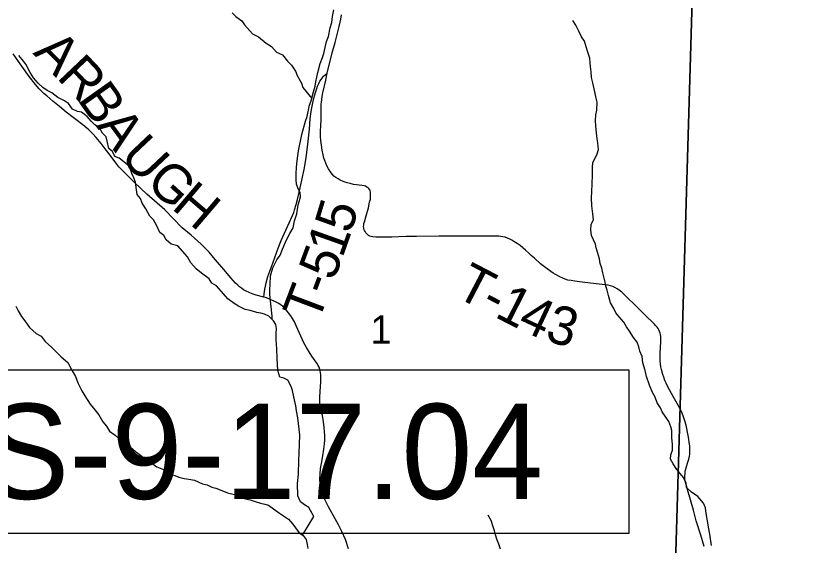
# Model space of a CAD drawing. Extents: x 0 to 34, y 0 to 22.
# Drawn here: x 14.55 to 15.724, y 18.969 to 19.748 of the extents above; entities that cross this region are included whole.
import ezdxf

# ---------------------------------------------------------------- set-up
doc = ezdxf.new("R2010")
doc.units = 0
for name, color, linetype in [('GM_X_Corporation', 7, 'Continuous'), ('GM_X_Minor_River', 7, 'Continuous'), ('GM_X_Section_Text', 7, 'Continuous'), ('GM_X_Township_Road', 7, 'Continuous'), ('GM_X_Township_Road_Text', 7, 'Continuous'), ('SH_Text', 7, 'Continuous')]:
    doc.layers.add(name, color=color, linetype=linetype)

msp = doc.modelspace()

# ---------------------------------------------------------------- linework, layer by layer
at = {"layer": 'GM_X_Corporation'}
for points in [[(14.532, 19.9321), (15.5496, 19.9206), (15.5197, 18.9088), (14.5125, 18.9236)], [(16.7598, 19.9006), (16.7485, 18.8896), (16.5138, 18.8938), (15.5197, 18.9088), (15.5496, 19.9206)]]:
    msp.add_lwpolyline(points, close=True, dxfattribs=at)
at = {"layer": 'GM_X_Minor_River'}
for points in [[(14.927, 19.301), (14.927, 19.306), (14.9234, 19.338), (14.9234, 19.3459), (14.9238, 19.3524), (14.9242, 19.3653), (14.9277, 19.3771), (14.9338, 19.3888), (14.9388, 19.3957), (14.9422, 19.4044), (14.948, 19.4184), (14.953, 19.4279), (14.9579, 19.4362), (14.9595, 19.4465), (14.9633, 19.4567), (14.9653, 19.47), (14.9672, 19.4761), (14.9684, 19.4818), (14.968, 19.4879), (14.965, 19.4936), (14.9628, 19.5004), (14.962, 19.5069), (14.9621, 19.5153), (14.9625, 19.5251), (14.9637, 19.5346), (14.9656, 19.5495), (14.9703, 19.5734), (14.9757, 19.5931), (14.9784, 19.5999), (14.9819, 19.6167), (14.9842, 19.6231), (14.9876, 19.6364), (14.99, 19.6444), (14.9911, 19.6508), (14.9942, 19.6645), (14.9977, 19.6778), (15.0011, 19.6869), (15.0027, 19.6926), (15.0066, 19.7104), (15.01, 19.7176), (15.0123, 19.7305), (15.0146, 19.7385), (15.0154, 19.7469), (15.0178, 19.7567)], [(14.8679, 19.7523), (14.8735, 19.747), (14.8822, 19.7409), (14.886, 19.7348), (14.8981, 19.7215), (14.9068, 19.7172), (14.9181, 19.7077), (14.9257, 19.7031), (14.9333, 19.6947), (14.9423, 19.6905), (14.9495, 19.6814), (14.9552, 19.6753), (14.9612, 19.6665), (14.9638, 19.6604), (14.9699, 19.649), (14.9721, 19.6425), (14.985, 19.6265)], [(15.4049, 19.609), (15.405, 19.6208), (15.4039, 19.6269), (15.4016, 19.6364), (15.3986, 19.6494), (15.3968, 19.6573), (15.3961, 19.6657), (15.3953, 19.6733), (15.395, 19.679), (15.3942, 19.6858), (15.3909, 19.6961), (15.3864, 19.7106), (15.3822, 19.7174), (15.3781, 19.7254), (15.3736, 19.7342), (15.3694, 19.741)], [(14.9717, 18.9836), (14.9884, 19.0113), (14.9808, 19.0243), (14.9744, 19.0281), (14.9687, 19.0327), (14.9646, 19.0414), (14.9643, 19.0597), (14.9655, 19.0733), (14.9663, 19.0942), (14.9668, 19.1041), (14.9672, 19.1178), (14.9676, 19.1307), (14.9665, 19.1398), (14.9647, 19.1562), (14.9625, 19.1668), (14.9617, 19.174), (14.9588, 19.1874), (14.9569, 19.1965), (14.9547, 19.2026), (14.9498, 19.2117), (14.9441, 19.2148), (14.938, 19.2163), (14.9354, 19.2262), (14.9343, 19.2444), (14.9336, 19.2577), (14.9326, 19.2718), (14.9326, 19.2805), (14.9334, 19.2878), (14.9323, 19.2935), (14.9289, 19.2992), (14.9217, 19.306), (14.9157, 19.3091), (14.91, 19.3106), (14.9043, 19.3114), (14.8944, 19.3141), (14.8872, 19.3157), (14.8774, 19.3206), (14.8709, 19.3245), (14.8615, 19.3313), (14.8551, 19.339), (14.8449, 19.3508), (14.8381, 19.3546), (14.8339, 19.3611), (14.823, 19.3691), (14.815, 19.3756), (14.8071, 19.3847), (14.8022, 19.3931), (14.7882, 19.4095), (14.778, 19.4122), (14.7708, 19.4183), (14.7674, 19.4248), (14.7617, 19.429), (14.7569, 19.4389), (14.752, 19.4476), (14.747, 19.4533), (14.741, 19.464), (14.7354, 19.4724), (14.7331, 19.4792), (14.7282, 19.4853), (14.7271, 19.4918), (14.7256, 19.5032), (14.7234, 19.5097), (14.7204, 19.5158), (14.7174, 19.5257), (14.7083, 19.5333), (14.7015, 19.5386), (14.6954, 19.5409), (14.6921, 19.5482), (14.6864, 19.5527), (14.6842, 19.5634), (14.6827, 19.5699), (14.677, 19.5752), (14.6725, 19.5832), (14.666, 19.5878), (14.6604, 19.5931), (14.6547, 19.6), (14.6464, 19.6061), (14.6403, 19.6072), (14.6331, 19.6107), (14.6271, 19.6191), (14.6214, 19.6229), (14.6116, 19.6279), (14.6025, 19.6347), (14.5957, 19.6382), (14.5893, 19.6424), (14.5825, 19.6489), (14.5757, 19.6569), (14.5708, 19.6645), (14.5644, 19.6771), (14.5587, 19.6839), (14.5538, 19.6896)], [(15.5736, 18.9682), (15.5711, 18.9849), (15.5688, 18.9955), (15.5681, 19.002), (15.5655, 19.0153), (15.5648, 19.0237), (15.5618, 19.0309), (15.5531, 19.0404), (15.544, 19.0469), (15.5368, 19.0538), (15.5361, 19.0603), (15.532, 19.0683), (15.5225, 19.0804), (15.5169, 19.0884), (15.5131, 19.0953), (15.5135, 19.1018), (15.5158, 19.1086), (15.5162, 19.1169), (15.5151, 19.1272), (15.5152, 19.1375), (15.5137, 19.1432), (15.5107, 19.1508), (15.505, 19.1588), (15.5009, 19.1653), (15.4983, 19.171), (15.4937, 19.1782), (15.4904, 19.1866), (15.4866, 19.1938), (15.4821, 19.2045), (15.4776, 19.217), (15.4757, 19.2258), (15.4724, 19.2372), (15.4716, 19.2467), (15.4679, 19.2547), (15.4664, 19.2608), (15.4638, 19.2676), (15.4585, 19.2748), (15.4528, 19.284), (15.4483, 19.2905), (15.4442, 19.2973), (15.4377, 19.3049), (15.4325, 19.3107), (15.4295, 19.3171), (15.4249, 19.3255), (15.4219, 19.3362), (15.4201, 19.3441), (15.4178, 19.3502), (15.4163, 19.3578), (15.4149, 19.3639), (15.4134, 19.3696), (15.4119, 19.3765), (15.4096, 19.3837), (15.4085, 19.3905), (15.4055, 19.4001), (15.4037, 19.4065), (15.4025, 19.4122), (15.3999, 19.4183), (15.3969, 19.4248), (15.3958, 19.4331), (15.3962, 19.4415), (15.4, 19.4476), (15.3989, 19.4567), (15.3975, 19.4685), (15.3968, 19.4806), (15.3972, 19.4886), (15.398, 19.5012), (15.3984, 19.5133), (15.3985, 19.5255), (15.3989, 19.5316), (15.405, 19.5448), (15.4069, 19.5513), (15.4062, 19.5612), (15.4051, 19.5669), (15.4037, 19.5802), (15.4033, 19.5866), (15.4029, 19.5935), (15.4034, 19.6026), (15.4049, 19.609)], [(14.5495, 19.3207), (14.5529, 19.3138), (14.5578, 19.3055), (14.5627, 19.299), (14.5695, 19.2891), (14.5797, 19.2803), (14.5869, 19.2765), (14.593, 19.2688), (14.6028, 19.2597), (14.6164, 19.246), (14.6262, 19.2379), (14.6319, 19.2265), (14.6375, 19.217), (14.6409, 19.2079), (14.6439, 19.2018), (14.6469, 19.1961), (14.651, 19.1888), (14.659, 19.1763), (14.6661, 19.1679), (14.6718, 19.1606), (14.6778, 19.1504), (14.6831, 19.1439), (14.6876, 19.1367), (14.6956, 19.1309), (14.705, 19.1225), (14.7122, 19.1179), (14.7183, 19.113), (14.7258, 19.1069), (14.733, 19.1015), (14.7398, 19.0958), (14.7455, 19.0927), (14.7572, 19.0843), (14.7671, 19.0801), (14.7765, 19.0736), (14.7837, 19.0713), (14.7894, 19.069), (14.7974, 19.0671), (14.8042, 19.0663), (14.8125, 19.0644), (14.8243, 19.059), (14.8311, 19.0575), (14.8379, 19.0544), (14.844, 19.0529), (14.8504, 19.0502), (14.861, 19.046), (14.8712, 19.0433), (14.8834, 19.0379), (14.8947, 19.0356), (14.9019, 19.0333), (14.9095, 19.0306), (14.916, 19.0294), (14.9216, 19.0279), (14.9288, 19.0225), (14.9375, 19.0161), (14.9451, 19.0111), (14.9508, 19.0073), (14.9572, 19), (14.9613, 18.9943), (14.9666, 18.9871), (14.9727, 18.9829), (14.9768, 18.9772), (14.9783, 18.9699), (14.9794, 18.9642)], [(15.2629, 18.9632), (15.2606, 18.9704), (15.2576, 18.9777), (15.2554, 18.9841), (15.2539, 18.9898), (15.252, 18.9959), (15.249, 19.0051), (15.2449, 19.013)]]:
    msp.add_lwpolyline(points, dxfattribs=at)
at = {"layer": 'GM_X_Township_Road'}
for points in [[(14.9992, 19.6187), (14.9993, 19.6206), (15.0006, 19.6295), (15.0015, 19.6347), (15.0056, 19.6536), (15.0077, 19.6637), (15.0153, 19.6938), (15.0196, 19.7087), (15.0254, 19.7324), (15.0279, 19.743), (15.0291, 19.7498)], [(14.9148, 19.3341), (14.9031, 19.337), (14.8974, 19.3389), (14.8929, 19.3407), (14.8886, 19.3428), (14.8848, 19.3449), (14.8816, 19.347), (14.879, 19.3491), (14.8762, 19.3514), (14.8728, 19.3544), (14.8693, 19.3583), (14.8662, 19.3623), (14.8558, 19.3746), (14.8464, 19.3855), (14.8407, 19.3925), (14.834, 19.4002), (14.8288, 19.4058), (14.8223, 19.412), (14.8076, 19.425), (14.7944, 19.4359), (14.7687, 19.4626), (14.7422, 19.4857), (14.7242, 19.5027), (14.7179, 19.509), (14.7124, 19.5144), (14.7085, 19.5184), (14.7051, 19.522), (14.7014, 19.526), (14.6982, 19.5298), (14.6882, 19.5428), (14.6809, 19.5522), (14.6751, 19.5602), (14.668, 19.5691), (14.6628, 19.5744), (14.6569, 19.5802), (14.6484, 19.5876), (14.6235, 19.6061), (14.6137, 19.6145), (14.6042, 19.6226), (14.5952, 19.6304), (14.5907, 19.634), (14.5838, 19.6406), (14.576, 19.6499), (14.5731, 19.6538), (14.5693, 19.6588), (14.5582, 19.6741), (14.5534, 19.6809), (14.5459, 19.6922)], [(14.9148, 19.3341), (14.9151, 19.3389), (14.916, 19.3459), (14.9168, 19.3502), (14.9181, 19.3552), (14.9207, 19.3643), (14.9235, 19.3722), (14.926, 19.3788), (14.9357, 19.4061), (14.9401, 19.4172), (14.9472, 19.4328), (14.9568, 19.4541), (14.9585, 19.4586), (14.9599, 19.4625), (14.9621, 19.4703), (14.9642, 19.4778), (14.9682, 19.4947), (14.9707, 19.5062), (14.9741, 19.5221), (14.9769, 19.539), (14.9795, 19.5594), (14.9819, 19.5815), (14.983, 19.5966), (14.9841, 19.6072), (14.9855, 19.6149), (14.9866, 19.6202), (14.989, 19.6301), (14.991, 19.6369), (14.9924, 19.6412), (14.9938, 19.6448), (14.9955, 19.6484), (14.9972, 19.6517), (14.9989, 19.6543), (15.0002, 19.6563), (15.0024, 19.6592), (15.0048, 19.6614), (15.0077, 19.6637)], [(15.4676, 19.3156), (15.4611, 19.322), (15.4488, 19.3342), (15.4414, 19.3412), (15.4377, 19.3443), (15.4348, 19.3463), (15.431, 19.3483), (15.428, 19.3495), (15.4246, 19.3507), (15.4213, 19.3514), (15.417, 19.3521), (15.4079, 19.3529), (15.3868, 19.3555), (15.3792, 19.3564), (15.3722, 19.3574), (15.3668, 19.3583), (15.3621, 19.359), (15.3583, 19.3603), (15.3544, 19.3619), (15.3503, 19.3638), (15.3468, 19.3657), (15.3437, 19.3675), (15.3406, 19.3695), (15.3316, 19.3756), (15.3255, 19.3801), (15.322, 19.3829), (15.3129, 19.3912), (15.3082, 19.3955), (15.3042, 19.3992), (15.2998, 19.4032), (15.2959, 19.4066), (15.292, 19.4098), (15.2872, 19.4132), (15.2826, 19.4161), (15.2795, 19.4179), (15.2765, 19.4195), (15.2733, 19.421), (15.2697, 19.4222), (15.2663, 19.423), (15.2606, 19.4237), (15.2553, 19.4238), (15.2131, 19.4236), (15.1867, 19.4238), (15.172, 19.4239), (15.1392, 19.4234), (15.1239, 19.4231), (15.1134, 19.4228), (15.1031, 19.4225), (15.0962, 19.4224), (15.0792, 19.4225), (15.0751, 19.4229), (15.0727, 19.4232), (15.0706, 19.424), (15.0688, 19.4249), (15.0673, 19.426), (15.066, 19.4272), (15.0648, 19.4286), (15.0635, 19.4304), (15.0628, 19.4322), (15.062, 19.4343), (15.0616, 19.4361), (15.0614, 19.4379), (15.0616, 19.4402), (15.062, 19.4426), (15.0626, 19.445), (15.0652, 19.4538), (15.0684, 19.4653), (15.0703, 19.4737), (15.0714, 19.478), (15.0718, 19.4816), (15.0716, 19.4883), (15.0712, 19.4903), (15.0704, 19.4921), (15.0693, 19.4937), (15.0681, 19.4949), (15.0663, 19.4961), (15.0642, 19.4972), (15.0624, 19.4978), (15.0587, 19.4985), (15.0511, 19.4992), (15.0466, 19.5), (15.0417, 19.5011), (15.0371, 19.5024), (15.0315, 19.5044), (15.0269, 19.5064), (15.0238, 19.508), (15.0204, 19.5102), (15.0178, 19.5123), (15.0156, 19.5145), (15.0135, 19.5169), (15.0115, 19.52), (15.0097, 19.5228), (15.0074, 19.5273), (15.0058, 19.5312), (15.0042, 19.5353), (15.003, 19.5388), (15.0018, 19.5436), (15.0005, 19.5502), (14.9995, 19.5578), (14.9986, 19.5646), (14.9981, 19.5707), (14.998, 19.5786), (14.9985, 19.5855), (14.9988, 19.5962), (14.9992, 19.6187)], [(15.0393, 18.9634), (15.0347, 18.9773), (15.0296, 18.9889), (15.0245, 18.9989), (15.0098, 19.0253), (15.0062, 19.0323), (15.0034, 19.0383), (15.002, 19.0418), (15.0008, 19.0462), (14.999, 19.0524), (14.9977, 19.0595), (14.9969, 19.0655), (14.9981, 19.0819), (14.9993, 19.0891), (15.0012, 19.1005), (15.0028, 19.1103), (15.0039, 19.1181), (15.0042, 19.1233), (15.0043, 19.1305), (15.004, 19.1356), (15.0035, 19.1428), (15.0021, 19.154), (15.0009, 19.1598), (14.9982, 19.1708), (14.9971, 19.1793), (14.9972, 19.187), (14.9973, 19.1952), (14.9986, 19.2094), (14.9987, 19.215), (14.9985, 19.2199), (14.9981, 19.2228), (14.9975, 19.2257), (14.997, 19.2277), (14.9958, 19.2309), (14.9946, 19.2334), (14.9928, 19.2366), (14.9851, 19.2473), (14.9827, 19.2509), (14.9773, 19.2597), (14.9737, 19.2668), (14.9627, 19.2907), (14.9597, 19.2978), (14.957, 19.3026), (14.9545, 19.3066), (14.951, 19.3111), (14.946, 19.3173), (14.9419, 19.3208), (14.9367, 19.3247), (14.9316, 19.3272), (14.9241, 19.3306), (14.9183, 19.3328), (14.9148, 19.3341)], [(15.5627, 18.9669), (15.5601, 18.9754), (15.5575, 18.9838), (15.5511, 19.0045), (15.5467, 19.0204), (15.538, 19.0511), (15.5361, 19.0581), (15.5349, 19.0632), (15.5344, 19.0677), (15.5349, 19.0779), (15.5361, 19.0826), (15.5383, 19.0898), (15.54, 19.0956), (15.5409, 19.0997), (15.5414, 19.1027), (15.5416, 19.1061), (15.5414, 19.115), (15.5408, 19.1202), (15.5399, 19.1251), (15.5389, 19.1305), (15.536, 19.1454), (15.5342, 19.1521), (15.5323, 19.1579), (15.5302, 19.1631), (15.5276, 19.1684), (15.5228, 19.1775), (15.517, 19.1878), (15.5093, 19.2019), (15.5065, 19.2074), (15.5049, 19.2115), (15.5031, 19.2163), (15.5018, 19.22), (15.4997, 19.2275), (15.4988, 19.2316), (15.4982, 19.2358), (15.4978, 19.2401), (15.498, 19.2517), (15.4991, 19.268), (15.4988, 19.2757), (15.4983, 19.2789), (15.4977, 19.2812), (15.4969, 19.2833), (15.4959, 19.2857), (15.4947, 19.2877), (15.4933, 19.2897), (15.4911, 19.2922), (15.4894, 19.294), (15.4749, 19.3084), (15.4676, 19.3156)]]:
    msp.add_lwpolyline(points, dxfattribs=at)
at = {"layer": 'SH_Text'}
msp.add_lwpolyline([(14.1914, 19.2265), (14.1914, 18.9865), (15.4525, 18.9865), (15.4525, 19.2265)], close=True, dxfattribs=at)

# ---------------------------------------------------------------- texts
at = {"layer": 'GM_X_Section_Text'}
msp.add_text('1', height=0.0419, rotation=0, dxfattribs=at).set_placement((15.0715, 19.2654))
at = {"layer": 'GM_X_Township_Road_Text'}
for s, rotation, p in [('A', 314.3638, (14.5737, 19.6927)), ('R', 313.4985, (14.6085, 19.6571)), ('B', 305.3476, (14.6393, 19.6249)), ('A', 306.0722, (14.6668, 19.5862)), ('U', 313.3162, (14.7012, 19.5398)), ('G', 317.659, (14.7389, 19.5001)), ('H', 319.5271, (14.7773, 19.4651)), ('5', 73.203, (15.0426, 19.4261)), ('1', 70.4233, (15.03, 19.3903)), ('5', 69.6202, (15.0175, 19.3566)), ('T', 332.4728, (15.1938, 19.3363)), ('-', 69.3907, (15.0092, 19.3346)), ('T', 69.3311, (14.9942, 19.2947)), ('1', 332.9941, (15.2527, 19.3056)), ('-', 332.5866, (15.2316, 19.3166)), ('4', 334.9474, (15.2858, 19.2888)), ('3', 343.952, (15.3266, 19.2706))]:
    msp.add_text(s, height=0.0568, rotation=rotation, dxfattribs=at).set_placement(p)
at = {"layer": 'SH_Text'}
msp.add_text('HAS-9-17.04', height=0.14, dxfattribs=at).set_placement((14.2432, 19.037))

doc.saveas('drawing.dxf')
